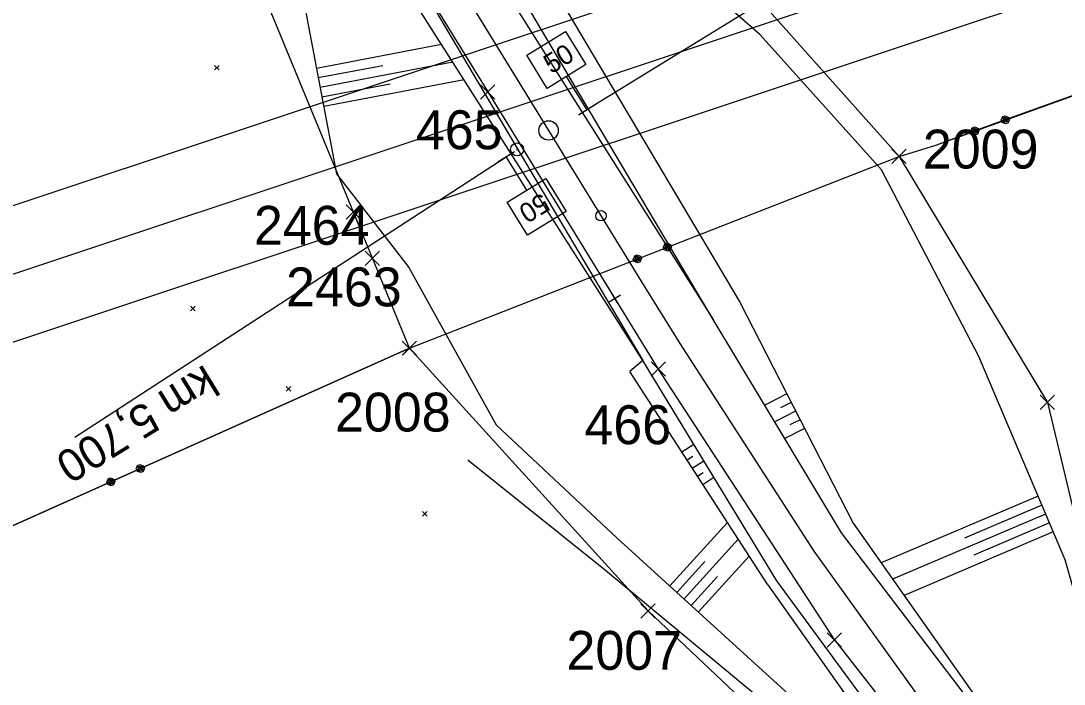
# Model space of a CAD drawing. Extents: x -866402 to -860377, y -1041908 to -1038598.
# Drawn here: x -864732.9 to -864652.3, y -1041379.2 to -1041328 of the extents above; entities that cross this region are included whole.
import ezdxf

# ---------------------------------------------------------------- set-up
doc = ezdxf.new("R2010")
doc.units = 0
for name, color, linetype in [('CD-budouci SZDC', 7, 'Continuous'), ('PS 02 trasa', 7, 'Continuous'), ('SZDC', 7, 'Continuous'), ('Vrstva 1', 7, 'Continuous'), ('Vrstva 48', 7, 'Continuous'), ('Vrstva 49', 7, 'Continuous'), ('Vrstva 5', 7, 'Continuous'), ('Vrstva 55', 7, 'Continuous'), ('Vrstva 60', 7, 'Continuous'), ('Vrstva 7', 7, 'Continuous')]:
    doc.layers.add(name, color=color, linetype=linetype)

msp = doc.modelspace()

# ---------------------------------------------------------------- linework, layer by layer
at = {"layer": 'CD-budouci SZDC'}
for points in [[(-864665.06, -1041338.43), (-864653.609, -1041357.419), (-864647.62, -1041382.33), (-864624.03, -1041399.3), (-864606.07, -1041416.92), (-864555.64, -1041449.33), (-864516.78, -1041457.92), (-864499.9, -1041462.62), (-864479.393, -1041454.553)], [(-864511.175, -1041504.766), (-864592.42, -1041468.06), (-864623.79, -1041463.38), (-864639.952, -1041446.086), (-864656.45, -1041414.71), (-864663.56, -1041393.24), (-864684.432, -1041373.516), (-864702.863, -1041353.237)]]:
    msp.add_lwpolyline(points, dxfattribs=at)
at = {"layer": 'PS 02 trasa'}
msp.add_lwpolyline([(-864722.992, -1041290.927), (-864709.891, -1041312.256), (-864696.818, -1041333.455), (-864683.647, -1041354.845), (-864669.989, -1041375.841), (-864670.047, -1041375.753), (-864654.196, -1041396.064), (-864636.993, -1041413.96), (-864617.087, -1041430.25), (-864595.729, -1041443.847), (-864573.114, -1041455.135), (-864549.386, -1041463.847), (-864525.459, -1041469.721), (-864500.135, -1041472.829), (-864472.89, -1041473.438), (-864449.699, -1041470.862), (-864425.036, -1041465.796), (-864401.282, -1041457.793)], dxfattribs=at)
at = {"layer": 'SZDC'}
for points in [[(-864707.88, -1041292.731), (-864695.12, -1041304.731), (-864665.06, -1041338.43)], [(-864702.863, -1041353.237), (-864705.721, -1041346.294), (-864707.188, -1041342.73), (-864718.497, -1041315.253), (-864719.377, -1041313.116), (-864722.414, -1041309.283), (-864732.75, -1041296.241)]]:
    msp.add_lwpolyline(points, dxfattribs=at)
at = {"layer": 'Vrstva 1'}
for p, q in [((-864638.85, -1041329.15), (-864655.86, -1041335.25)), ((-864638.85, -1041329.15), (-864655.86, -1041335.25)), ((-864655.86, -1041335.25), (-864659.92, -1041336.73)), ((-864655.86, -1041335.25), (-864659.92, -1041336.73)), ((-864657.172, -1041335.622), (-864657.053, -1041335.365)), ((-864657.172, -1041335.622), (-864657.053, -1041335.365)), ((-864657.104, -1041335.809), (-864657.172, -1041335.622)), ((-864657.104, -1041335.809), (-864657.172, -1041335.622)), ((-864657.078, -1041335.587), (-864657.01, -1041335.775)), ((-864657.078, -1041335.587), (-864657.01, -1041335.775)), ((-864657.053, -1041335.365), (-864656.865, -1041335.297)), ((-864657.053, -1041335.365), (-864656.865, -1041335.297)), ((-864657.018, -1041335.459), (-864656.831, -1041335.391)), ((-864657.018, -1041335.459), (-864656.831, -1041335.391)), ((-864656.881, -1041335.835), (-864657.018, -1041335.459)), ((-864656.881, -1041335.835), (-864657.018, -1041335.459)), ((-864656.925, -1041335.425), (-864656.788, -1041335.801)), ((-864656.925, -1041335.425), (-864656.788, -1041335.801)), ((-864656.865, -1041335.297), (-864656.608, -1041335.416)), ((-864656.865, -1041335.297), (-864656.608, -1041335.416)), ((-864656.831, -1041335.391), (-864656.694, -1041335.766)), ((-864656.831, -1041335.391), (-864656.694, -1041335.766)), ((-864656.634, -1041335.638), (-864656.702, -1041335.45)), ((-864656.634, -1041335.638), (-864656.702, -1041335.45)), ((-864656.694, -1041335.766), (-864656.634, -1041335.638)), ((-864656.694, -1041335.766), (-864656.634, -1041335.638)), ((-864656.54, -1041335.604), (-864656.659, -1041335.86)), ((-864656.54, -1041335.604), (-864656.659, -1041335.86)), ((-864656.608, -1041335.416), (-864656.54, -1041335.604)), ((-864656.608, -1041335.416), (-864656.54, -1041335.604)), ((-864659.521, -1041336.478), (-864659.402, -1041336.221)), ((-864659.521, -1041336.478), (-864659.402, -1041336.221)), ((-864659.452, -1041336.666), (-864659.521, -1041336.478)), ((-864659.452, -1041336.666), (-864659.521, -1041336.478)), ((-864659.427, -1041336.444), (-864659.358, -1041336.631)), ((-864659.427, -1041336.444), (-864659.358, -1041336.631)), ((-864659.402, -1041336.221), (-864659.214, -1041336.153)), ((-864659.402, -1041336.221), (-864659.214, -1041336.153)), ((-864659.367, -1041336.315), (-864659.179, -1041336.247)), ((-864659.367, -1041336.315), (-864659.179, -1041336.247)), ((-864659.23, -1041336.691), (-864659.367, -1041336.315)), ((-864659.23, -1041336.691), (-864659.367, -1041336.315)), ((-864659.273, -1041336.281), (-864659.136, -1041336.657)), ((-864659.273, -1041336.281), (-864659.136, -1041336.657)), ((-864659.214, -1041336.153), (-864658.957, -1041336.272)), ((-864659.214, -1041336.153), (-864658.957, -1041336.272)), ((-864659.179, -1041336.247), (-864659.042, -1041336.623)), ((-864659.179, -1041336.247), (-864659.042, -1041336.623)), ((-864658.983, -1041336.494), (-864659.051, -1041336.307)), ((-864658.983, -1041336.494), (-864659.051, -1041336.307)), ((-864659.042, -1041336.623), (-864658.983, -1041336.494)), ((-864659.042, -1041336.623), (-864658.983, -1041336.494)), ((-864658.889, -1041336.46), (-864659.008, -1041336.717)), ((-864658.889, -1041336.46), (-864659.008, -1041336.717)), ((-864658.957, -1041336.272), (-864658.889, -1041336.46)), ((-864658.957, -1041336.272), (-864658.889, -1041336.46)), ((-864656.847, -1041335.929), (-864657.104, -1041335.809)), ((-864656.847, -1041335.929), (-864657.104, -1041335.809)), ((-864657.01, -1041335.775), (-864656.881, -1041335.835)), ((-864657.01, -1041335.775), (-864656.881, -1041335.835)), ((-864656.659, -1041335.86), (-864656.847, -1041335.929)), ((-864656.659, -1041335.86), (-864656.847, -1041335.929)), ((-864662.21, -1041337.57), (-864659.92, -1041336.73)), ((-864662.21, -1041337.57), (-864659.92, -1041336.73)), ((-864659.196, -1041336.785), (-864659.452, -1041336.666)), ((-864659.196, -1041336.785), (-864659.452, -1041336.666)), ((-864659.358, -1041336.631), (-864659.23, -1041336.691)), ((-864659.358, -1041336.631), (-864659.23, -1041336.691)), ((-864659.008, -1041336.717), (-864659.196, -1041336.785)), ((-864659.008, -1041336.717), (-864659.196, -1041336.785)), ((-864665.06, -1041338.43), (-864662.21, -1041337.57)), ((-864665.06, -1041338.43), (-864662.21, -1041337.57)), ((-864702.863, -1041353.237), (-864665.06, -1041338.43)), ((-864702.863, -1041353.237), (-864665.06, -1041338.43)), ((-864683.253, -1041345.448), (-864683.14, -1041345.189)), ((-864683.253, -1041345.448), (-864683.14, -1041345.189)), ((-864683.16, -1041345.412), (-864683.087, -1041345.598)), ((-864683.16, -1041345.412), (-864683.087, -1041345.598)), ((-864683.14, -1041345.189), (-864682.954, -1041345.116)), ((-864683.14, -1041345.189), (-864682.954, -1041345.116)), ((-864683.103, -1041345.282), (-864682.917, -1041345.209)), ((-864683.103, -1041345.282), (-864682.917, -1041345.209)), ((-864682.957, -1041345.655), (-864683.103, -1041345.282)), ((-864682.957, -1041345.655), (-864683.103, -1041345.282)), ((-864683.01, -1041345.246), (-864682.864, -1041345.618)), ((-864683.01, -1041345.246), (-864682.864, -1041345.618)), ((-864682.954, -1041345.116), (-864682.694, -1041345.23)), ((-864682.954, -1041345.116), (-864682.694, -1041345.23)), ((-864682.917, -1041345.209), (-864682.771, -1041345.582)), ((-864682.917, -1041345.209), (-864682.771, -1041345.582)), ((-864682.715, -1041345.452), (-864682.787, -1041345.266)), ((-864682.715, -1041345.452), (-864682.787, -1041345.266)), ((-864682.621, -1041345.416), (-864682.735, -1041345.675)), ((-864682.621, -1041345.416), (-864682.735, -1041345.675)), ((-864682.694, -1041345.23), (-864682.621, -1041345.416)), ((-864682.694, -1041345.23), (-864682.621, -1041345.416)), ((-864685.581, -1041346.36), (-864685.468, -1041346.101)), ((-864685.581, -1041346.36), (-864685.468, -1041346.101)), ((-864685.468, -1041346.101), (-864685.281, -1041346.028)), ((-864685.468, -1041346.101), (-864685.281, -1041346.028)), ((-864685.431, -1041346.194), (-864685.245, -1041346.121)), ((-864685.431, -1041346.194), (-864685.245, -1041346.121)), ((-864685.285, -1041346.567), (-864685.431, -1041346.194)), ((-864685.285, -1041346.567), (-864685.431, -1041346.194)), ((-864685.338, -1041346.158), (-864685.192, -1041346.53)), ((-864685.338, -1041346.158), (-864685.192, -1041346.53)), ((-864685.281, -1041346.028), (-864685.022, -1041346.141)), ((-864685.281, -1041346.028), (-864685.022, -1041346.141)), ((-864685.245, -1041346.121), (-864685.099, -1041346.494)), ((-864685.245, -1041346.121), (-864685.099, -1041346.494)), ((-864685.042, -1041346.364), (-864685.115, -1041346.178)), ((-864685.042, -1041346.364), (-864685.115, -1041346.178)), ((-864685.022, -1041346.141), (-864684.949, -1041346.328)), ((-864685.022, -1041346.141), (-864684.949, -1041346.328)), ((-864683.18, -1041345.635), (-864683.253, -1041345.448)), ((-864683.18, -1041345.635), (-864683.253, -1041345.448)), ((-864682.921, -1041345.748), (-864683.18, -1041345.635)), ((-864682.921, -1041345.748), (-864683.18, -1041345.635)), ((-864683.087, -1041345.598), (-864682.957, -1041345.655)), ((-864683.087, -1041345.598), (-864682.957, -1041345.655)), ((-864682.735, -1041345.675), (-864682.921, -1041345.748)), ((-864682.735, -1041345.675), (-864682.921, -1041345.748)), ((-864682.771, -1041345.582), (-864682.715, -1041345.452)), ((-864682.771, -1041345.582), (-864682.715, -1041345.452)), ((-864685.508, -1041346.546), (-864685.581, -1041346.36)), ((-864685.508, -1041346.546), (-864685.581, -1041346.36)), ((-864685.249, -1041346.66), (-864685.508, -1041346.546)), ((-864685.249, -1041346.66), (-864685.508, -1041346.546)), ((-864685.488, -1041346.324), (-864685.415, -1041346.51)), ((-864685.488, -1041346.324), (-864685.415, -1041346.51)), ((-864685.415, -1041346.51), (-864685.285, -1041346.567)), ((-864685.415, -1041346.51), (-864685.285, -1041346.567)), ((-864685.062, -1041346.587), (-864685.249, -1041346.66)), ((-864685.062, -1041346.587), (-864685.249, -1041346.66)), ((-864685.099, -1041346.494), (-864685.042, -1041346.364)), ((-864685.099, -1041346.494), (-864685.042, -1041346.364)), ((-864684.949, -1041346.328), (-864685.062, -1041346.587)), ((-864684.949, -1041346.328), (-864685.062, -1041346.587)), ((-864746.41, -1041372.72), (-864702.863, -1041353.237)), ((-864746.41, -1041372.72), (-864702.863, -1041353.237)), ((-864723.947, -1041362.56), (-864723.846, -1041362.296)), ((-864723.947, -1041362.56), (-864723.846, -1041362.296)), ((-864723.846, -1041362.296), (-864723.664, -1041362.214)), ((-864723.846, -1041362.296), (-864723.664, -1041362.214)), ((-864723.805, -1041362.387), (-864723.623, -1041362.306)), ((-864723.805, -1041362.387), (-864723.623, -1041362.306)), ((-864723.664, -1041362.214), (-864723.399, -1041362.315)), ((-864723.664, -1041362.214), (-864723.399, -1041362.315)), ((-864723.623, -1041362.306), (-864723.459, -1041362.671)), ((-864723.623, -1041362.306), (-864723.459, -1041362.671)), ((-864723.399, -1041362.315), (-864723.318, -1041362.498)), ((-864723.399, -1041362.315), (-864723.318, -1041362.498)), ((-864723.865, -1041362.743), (-864723.947, -1041362.56)), ((-864723.865, -1041362.743), (-864723.947, -1041362.56)), ((-864723.601, -1041362.844), (-864723.865, -1041362.743)), ((-864723.601, -1041362.844), (-864723.865, -1041362.743)), ((-864723.856, -1041362.519), (-864723.774, -1041362.702)), ((-864723.856, -1041362.519), (-864723.774, -1041362.702)), ((-864723.642, -1041362.752), (-864723.805, -1041362.387)), ((-864723.642, -1041362.752), (-864723.805, -1041362.387)), ((-864723.774, -1041362.702), (-864723.642, -1041362.752)), ((-864723.774, -1041362.702), (-864723.642, -1041362.752)), ((-864723.714, -1041362.346), (-864723.551, -1041362.712)), ((-864723.714, -1041362.346), (-864723.551, -1041362.712)), ((-864723.419, -1041362.762), (-864723.601, -1041362.844)), ((-864723.419, -1041362.762), (-864723.601, -1041362.844)), ((-864723.409, -1041362.539), (-864723.491, -1041362.356)), ((-864723.409, -1041362.539), (-864723.491, -1041362.356)), ((-864723.459, -1041362.671), (-864723.409, -1041362.539)), ((-864723.459, -1041362.671), (-864723.409, -1041362.539)), ((-864723.318, -1041362.498), (-864723.419, -1041362.762)), ((-864723.318, -1041362.498), (-864723.419, -1041362.762)), ((-864726.229, -1041363.581), (-864726.128, -1041363.317)), ((-864726.229, -1041363.581), (-864726.128, -1041363.317)), ((-864726.147, -1041363.764), (-864726.229, -1041363.581)), ((-864726.147, -1041363.764), (-864726.229, -1041363.581)), ((-864725.883, -1041363.865), (-864726.147, -1041363.764)), ((-864725.883, -1041363.865), (-864726.147, -1041363.764)), ((-864726.138, -1041363.54), (-864726.056, -1041363.723)), ((-864726.138, -1041363.54), (-864726.056, -1041363.723)), ((-864726.128, -1041363.317), (-864725.946, -1041363.235)), ((-864726.128, -1041363.317), (-864725.946, -1041363.235)), ((-864726.087, -1041363.408), (-864725.905, -1041363.327)), ((-864726.087, -1041363.408), (-864725.905, -1041363.327)), ((-864725.924, -1041363.773), (-864726.087, -1041363.408)), ((-864725.924, -1041363.773), (-864726.087, -1041363.408)), ((-864726.056, -1041363.723), (-864725.924, -1041363.773)), ((-864726.056, -1041363.723), (-864725.924, -1041363.773)), ((-864725.996, -1041363.367), (-864725.833, -1041363.733)), ((-864725.996, -1041363.367), (-864725.833, -1041363.733)), ((-864725.946, -1041363.235), (-864725.681, -1041363.336)), ((-864725.946, -1041363.235), (-864725.681, -1041363.336)), ((-864725.905, -1041363.327), (-864725.741, -1041363.692)), ((-864725.905, -1041363.327), (-864725.741, -1041363.692)), ((-864725.701, -1041363.783), (-864725.883, -1041363.865)), ((-864725.701, -1041363.783), (-864725.883, -1041363.865)), ((-864725.691, -1041363.56), (-864725.773, -1041363.377)), ((-864725.691, -1041363.56), (-864725.773, -1041363.377)), ((-864725.741, -1041363.692), (-864725.691, -1041363.56)), ((-864725.741, -1041363.692), (-864725.691, -1041363.56)), ((-864725.6, -1041363.519), (-864725.701, -1041363.783)), ((-864725.6, -1041363.519), (-864725.701, -1041363.783)), ((-864725.681, -1041363.336), (-864725.6, -1041363.519)), ((-864725.681, -1041363.336), (-864725.6, -1041363.519))]:
    msp.add_line(p, q, dxfattribs=at)
for points in [[(-864678.843, -1041637.084), (-863881.875, -1041371.706), (-863975.703, -1041089.927), (-864772.671, -1041355.305)], [(-863888.199, -1041368.542), (-864675.679, -1041630.76), (-864766.347, -1041358.469), (-863978.867, -1041096.25)], [(-864672.518, -1041624.443), (-864089.016, -1041430.146), (-864176.529, -1041167.333), (-864760.03, -1041361.63)]]:
    msp.add_lwpolyline(points, close=True, dxfattribs=at)
for points in [[(-864716.892, -1041296.273), (-864708.057, -1041310.483), (-864706.352, -1041313.25), (-864684.947, -1041348.104)], [(-864684.947, -1041348.104), (-864681.99, -1041352.872), (-864671.641, -1041368.894), (-864660.545, -1041384.312)]]:
    msp.add_lwpolyline(points, dxfattribs=at)
msp.add_circle((-864688.074, -1041343.012), 0.4, dxfattribs=at)
at = {"layer": 'Vrstva 48'}
for p, q in [((-864710.038, -1041331.618), (-864700.372, -1041329.785)), ((-864709.899, -1041332.355), (-864704.919, -1041331.411)), ((-864709.759, -1041333.092), (-864699.505, -1041331.148)), ((-864709.479, -1041334.566), (-864698.638, -1041332.51)), ((-864709.619, -1041333.829), (-864704.345, -1041332.829)), ((-864673.73, -1041356.759), (-864675.432, -1041357.633)), ((-864673.387, -1041357.426), (-864674.216, -1041357.852)), ((-864673.045, -1041358.093), (-864674.657, -1041358.922)), ((-864672.702, -1041358.76), (-864673.486, -1041359.163)), ((-864672.359, -1041359.428), (-864673.882, -1041360.21)), ((-864681.832, -1041361.234), (-864680.91, -1041360.638)), ((-864681.425, -1041361.864), (-864680.972, -1041361.572)), ((-864681.018, -1041362.494), (-864680.129, -1041361.92)), ((-864680.611, -1041363.124), (-864680.175, -1041362.842)), ((-864680.204, -1041363.754), (-864679.348, -1041363.201)), ((-864654.325, -1041364.657), (-864666.442, -1041369.808)), ((-864654.032, -1041365.347), (-864660.016, -1041367.891)), ((-864653.739, -1041366.037), (-864665.557, -1041371.062)), ((-864682.766, -1041371.579), (-864678.31, -1041366.684)), ((-864653.445, -1041366.728), (-864659.28, -1041369.208)), ((-864653.152, -1041367.418), (-864664.673, -1041372.316)), ((-864681.657, -1041372.589), (-864677.468, -1041367.988)), ((-864680.548, -1041373.599), (-864676.626, -1041369.291)), ((-864682.212, -1041372.084), (-864680.05, -1041369.71)), ((-864681.103, -1041373.094), (-864679.075, -1041370.866))]:
    msp.add_line(p, q, dxfattribs=at)
at = {"layer": 'Vrstva 49'}
for p, q in [((-864717.902, -1041331.411), (-864717.548, -1041331.765)), ((-864717.902, -1041331.765), (-864717.548, -1041331.411)), ((-864719.752, -1041349.995), (-864719.398, -1041350.349)), ((-864719.752, -1041350.349), (-864719.398, -1041349.995)), ((-864684.836, -1041354.196), (-864685.839, -1041355.033)), ((-864675.194, -1041371.506), (-864685.839, -1041355.033)), ((-864712.377, -1041356.205), (-864712.023, -1041356.559)), ((-864712.377, -1041356.559), (-864712.023, -1041356.205)), ((-864701.853, -1041365.836), (-864701.499, -1041366.19)), ((-864701.853, -1041366.19), (-864701.499, -1041365.836))]:
    msp.add_line(p, q, dxfattribs=at)
for points in [[(-864642.097, -1041392.43), (-864648.644, -1041382.044), (-864652.237, -1041369.569), (-864658.908, -1041353.879), (-864666.425, -1041339.474), (-864675.789, -1041329.057), (-864688.052, -1041318.262), (-864703.419, -1041302.552), (-864705.87, -1041301.661)], [(-864705.87, -1041301.661), (-864677.362, -1041349.687), (-864668.597, -1041366.753), (-864657.663, -1041382.253), (-864652.622, -1041388.515), (-864648.777, -1041393.343)], [(-864648.777, -1041393.343), (-864653.196, -1041388.658), (-864658.037, -1041382.504), (-864669.504, -1041367.486), (-864679.41, -1041351.023), (-864702.962, -1041311.282), (-864706.567, -1041304.59)], [(-864707.736, -1041305.81), (-864704.126, -1041311.941), (-864679.41, -1041351.023)], [(-864715.672, -1041309.01), (-864713.763, -1041316.891), (-864711.039, -1041326.342), (-864708.492, -1041339.773), (-864702.915, -1041347.003), (-864696.162, -1041359.156), (-864686.82, -1041367.888), (-864664.971, -1041387.782), (-864661.042, -1041389.903)], [(-864712.896, -1041308.778), (-864708.149, -1041314.83), (-864684.836, -1041354.196)], [(-864684.836, -1041354.196), (-864709.228, -1041315.87), (-864712.88, -1041309.98)], [(-864661.042, -1041389.903), (-864663.298, -1041386.433), (-864674.482, -1041371.186), (-864684.836, -1041354.196)], [(-864661.411, -1041391.601), (-864665.858, -1041388.536), (-864687.721, -1041370.39), (-864698.356, -1041361.883)], [(-864675.194, -1041371.506), (-864664.154, -1041387.113), (-864661.042, -1041389.903)]]:
    msp.add_lwpolyline(points, dxfattribs=at)
at = {"layer": 'Vrstva 5'}
for p, q in [((-864689.167, -1041334.825), (-864645.189, -1041307.76)), ((-864689.167, -1041334.825), (-864690.737, -1041332.269)), ((-864689.806, -1041335.217), (-864688.528, -1041334.433)), ((-864694.752, -1041338.095), (-864696.03, -1041338.879)), ((-864695.391, -1041338.487), (-864728.701, -1041360.137)), ((-864695.391, -1041338.487), (-864693.821, -1041341.043))]:
    msp.add_line(p, q, dxfattribs=at)
for points in [[(-864689.246, -1041331.353), (-864692.228, -1041333.184), (-864693.798, -1041330.628), (-864690.816, -1041328.796)], [(-864695.312, -1041341.959), (-864692.33, -1041340.128), (-864690.76, -1041342.684), (-864693.742, -1041344.516)]]:
    msp.add_lwpolyline(points, close=True, dxfattribs=at)
at = {"layer": 'Vrstva 55'}
msp.add_line((-864702.863, -1041353.237), (-864746.41, -1041372.72), dxfattribs=at)
msp.add_lwpolyline([(-864702.863, -1041353.237), (-864665.06, -1041338.43), (-864662.21, -1041337.57), (-864638.85, -1041329.15)], dxfattribs=at)
at = {"layer": 'Vrstva 60'}
for p, q in [((-864696.368, -1041333.905), (-864697.368, -1041332.905)), ((-864696.368, -1041333.005), (-864697.368, -1041334.005)), ((-864697.268, -1041333.905), (-864696.268, -1041332.905)), ((-864697.268, -1041333.005), (-864696.268, -1041334.005)), ((-864696.818, -1041333.455), (-864696.818, -1041333.455)), ((-864664.61, -1041338.88), (-864665.61, -1041337.88)), ((-864664.61, -1041337.98), (-864665.61, -1041338.98)), ((-864665.51, -1041338.88), (-864664.51, -1041337.88)), ((-864665.51, -1041337.98), (-864664.51, -1041338.98)), ((-864665.06, -1041338.43), (-864665.06, -1041338.43)), ((-864706.738, -1041343.18), (-864707.738, -1041342.18)), ((-864707.638, -1041343.18), (-864706.638, -1041342.18)), ((-864706.738, -1041342.28), (-864707.738, -1041343.28)), ((-864707.638, -1041342.28), (-864706.638, -1041343.28)), ((-864707.188, -1041342.73), (-864707.188, -1041342.73)), ((-864705.271, -1041346.744), (-864706.271, -1041345.744)), ((-864705.271, -1041345.844), (-864706.271, -1041346.844)), ((-864706.171, -1041346.744), (-864705.171, -1041345.744)), ((-864706.171, -1041345.844), (-864705.171, -1041346.844)), ((-864705.721, -1041346.294), (-864705.721, -1041346.294)), ((-864702.413, -1041353.687), (-864703.413, -1041352.687)), ((-864702.413, -1041352.787), (-864703.413, -1041353.787)), ((-864703.313, -1041353.687), (-864702.313, -1041352.687)), ((-864703.313, -1041352.787), (-864702.313, -1041353.787)), ((-864702.863, -1041353.237), (-864702.863, -1041353.237)), ((-864683.197, -1041355.295), (-864684.197, -1041354.295)), ((-864683.197, -1041354.395), (-864684.197, -1041355.395)), ((-864684.097, -1041355.295), (-864683.097, -1041354.295)), ((-864684.097, -1041354.395), (-864683.097, -1041355.395)), ((-864683.647, -1041354.845), (-864683.647, -1041354.845)), ((-864653.159, -1041357.869), (-864654.159, -1041356.869)), ((-864653.159, -1041356.969), (-864654.159, -1041357.969)), ((-864654.059, -1041357.869), (-864653.059, -1041356.869)), ((-864654.059, -1041356.969), (-864653.059, -1041357.969)), ((-864653.609, -1041357.419), (-864653.609, -1041357.419)), ((-864683.982, -1041373.966), (-864684.982, -1041372.966)), ((-864683.982, -1041373.066), (-864684.982, -1041374.066)), ((-864684.882, -1041373.966), (-864683.882, -1041372.966)), ((-864684.882, -1041373.066), (-864683.882, -1041374.066)), ((-864684.432, -1041373.516), (-864684.432, -1041373.516)), ((-864669.597, -1041376.203), (-864670.597, -1041375.203)), ((-864670.497, -1041376.203), (-864669.497, -1041375.203)), ((-864669.597, -1041375.303), (-864670.597, -1041376.303)), ((-864670.497, -1041375.303), (-864669.497, -1041376.303)), ((-864670.047, -1041375.753), (-864670.047, -1041375.753))]:
    msp.add_line(p, q, dxfattribs=at)
at = {"layer": 'Vrstva 7'}
for p, q in [((-864694.601, -1041337.895), (-864694.501, -1041337.895)), ((-864687.427, -1041349.651), (-864686.575, -1041349.127)), ((-864686.739, -1041349.815), (-864687.263, -1041348.963))]:
    msp.add_line(p, q, dxfattribs=at)
for centre, radius in [((-864692.115, -1041336.433), 0.75), ((-864694.551, -1041337.895), 0.5)]:
    msp.add_circle(centre, radius, dxfattribs=at)

# ---------------------------------------------------------------- texts
at = {"layer": 'Vrstva 5'}
for s, height, rotation, p in [('50', 1.5, 31.55547, (-864691.908, -1041332.107)), ('50', 1.5, 211.55547, (-864692.65, -1041341.205)), ('km 5,700', 2.5, 211.55547, (-864718.655, -1041354.442))]:
    msp.add_text(s, height=height, rotation=rotation, dxfattribs=at).set_placement(p)
at = {"layer": 'Vrstva 60'}
for s, p in [('465', (-864702.366, -1041337.881)), ('2009', (-864663.219, -1041339.372)), ('2464', (-864714.867, -1041345.254)), ('2463', (-864712.381, -1041350.008)), ('2008', (-864708.605, -1041359.671)), ('466', (-864689.347, -1041360.646)), ('2007', (-864690.735, -1041378.063))]:
    msp.add_text(s, height=3, dxfattribs=at).set_placement(p)

doc.saveas('drawing.dxf')
